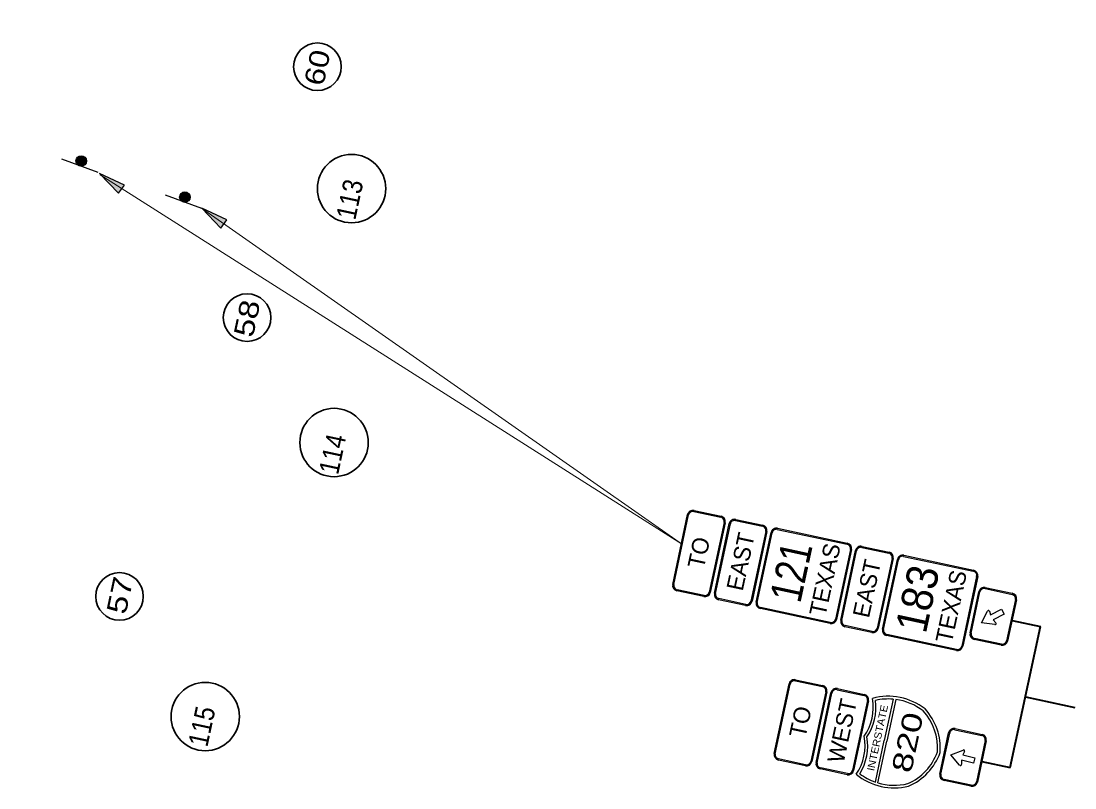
# Model space of a CAD drawing. Extents: x 2363411 to 2369702, y 6977197 to 6988655.
# Drawn here: x 2366110 to 2366856, y 6982468 to 6983011 of the extents above; entities that cross this region are included whole.
import ezdxf
from ezdxf.enums import TextEntityAlignment as Align

# ---------------------------------------------------------------- set-up
doc = ezdxf.new("R2010")
doc.units = 0
doc.header["$LTSCALE"] = 5.6
for name, color, linetype, lineweight in [('1', 7, 'Continuous', 25), ('17', 7, 'Continuous', 35), ('48', 7, 'Continuous', 25)]:
    doc.layers.add(name, color=color, linetype=linetype, lineweight=lineweight)

msp = doc.modelspace()

# ---------------------------------------------------------------- hatches: boundary and pattern name
at = {"layer": '1'}
for points in [[(2366155.643, 6982914.236, 1), (2366150.178, 6982909.153, 1)], [(2366165.758, 6982902.907), (2366179.263, 6982888.795), (2366183.462, 6982894.629)], [(2366228.992, 6982888.681, 1), (2366223.527, 6982883.598, 1)], [(2366238.192, 6982878.216), (2366251.697, 6982864.104), (2366255.896, 6982869.938)]]:
    msp.add_hatch(color=256, dxfattribs=at).paths.add_polyline_path(points)

# ---------------------------------------------------------------- linework, layer by layer
for p, q in [((2366138.982, 6982913.263), (2366164.676, 6982903.831)), ((2366212.331, 6982887.708), (2366238.025, 6982878.276)), ((2366727.069, 6982530.784), (2366720.803, 6982501.447)), ((2366728.961, 6982530.574), (2366722.651, 6982501.055)), ((2366714.536, 6982472.111), (2366720.803, 6982501.447)), ((2366716.344, 6982471.51), (2366722.651, 6982501.055))]:
    msp.add_line(p, q, dxfattribs=at)
at = {"layer": '1', "lineweight": 13}
for p in [(2366166.376, 6982901.97), (2366238.025, 6982878.276)]:
    msp.add_line(p, (2366578.036, 6982640.352), dxfattribs=at)
at = {"layer": '1'}
for points in [[(2366165.758, 6982902.907), (2366179.263, 6982888.795), (2366183.462, 6982894.629)], [(2366238.192, 6982878.216), (2366251.697, 6982864.104), (2366255.896, 6982869.938)]]:
    msp.add_lwpolyline(points, close=True, dxfattribs=at)
for centre in [(2366152.91, 6982911.694), (2366226.26, 6982886.139)]:
    msp.add_circle(centre, 3.732, dxfattribs=at)
at = {"layer": '1', "lineweight": 35}
msp.add_arc((2359877.328, 6985028.058), 6500, 337.9611, 358.49155, dxfattribs=at)
at = {"layer": '1'}
for centre, radius, start, end in [((2366677.098, 6982525.046), 35.984, 325.11936, 9.96967), ((2366677.098, 6982525.046), 37.874, 326.31727, 7.31411), ((2366723.753, 6982490.848), 41.954, 51.80216, 105.50453), ((2366723.753, 6982490.848), 40.064, 85.2486, 103.11335), ((2366723.753, 6982490.848), 40.064, 52.01869, 82.53068), ((2366719.762, 6982496.247), 38.808, 355.77701, 42.42339), ((2366719.762, 6982496.247), 40.698, 355.41087, 42.64677), ((2366671.265, 6982497.75), 35.984, 325.90827, 10.75858), ((2366671.265, 6982497.75), 37.874, 328.56383, 9.56067), ((2366721.973, 6982506.598), 38.808, 293.45455, 340.10093), ((2366721.973, 6982506.598), 40.698, 293.23117, 340.46707), ((2366727.823, 6982509.894), 40.064, 232.76459, 250.62934), ((2366727.823, 6982509.894), 41.954, 230.37341, 284.07578), ((2366727.823, 6982509.894), 40.064, 253.34726, 283.85925)]:
    msp.add_arc(centre, radius, start, end, dxfattribs=at)
at = {"layer": '17'}
for centre, radius in [((2366319.982, 6982978.4), 16.828), ((2366344.093, 6982892.118), 24.19), ((2366270.237, 6982800.82), 16.828), ((2366331.728, 6982712.428), 24.19), ((2366180.014, 6982603.484), 16.828), ((2366240.61, 6982518.479), 24.19)]:
    msp.add_circle(centre, radius, dxfattribs=at)
at = {"layer": '48'}
for p, q in [((2366586.297, 6982664.315), (2366605.38, 6982660.237)), ((2366571.199, 6982612.031), (2366581.739, 6982661.362)), ((2366571.95, 6982611.871), (2366582.491, 6982661.201)), ((2366586.137, 6982663.564), (2366605.219, 6982659.486)), ((2366615.664, 6982657.255), (2366634.746, 6982653.177)), ((2366615.824, 6982658.006), (2366634.907, 6982653.928)), ((2366607.582, 6982655.84), (2366597.041, 6982606.509)), ((2366608.333, 6982655.68), (2366597.792, 6982606.349)), ((2366600.726, 6982605.722), (2366611.267, 6982655.053)), ((2366601.477, 6982605.562), (2366612.018, 6982654.892)), ((2366637.109, 6982649.531), (2366626.568, 6982600.2)), ((2366637.86, 6982649.371), (2366627.319, 6982600.04)), ((2366645.191, 6982650.946), (2366694.521, 6982640.405)), ((2366645.351, 6982651.697), (2366694.682, 6982641.156)), ((2366630.253, 6982599.413), (2366640.794, 6982648.744)), ((2366631.004, 6982599.253), (2366641.545, 6982648.583)), ((2366696.884, 6982636.759), (2366686.343, 6982587.428)), ((2366697.635, 6982636.599), (2366687.094, 6982587.268)), ((2366690.028, 6982586.641), (2366700.568, 6982635.972)), ((2366690.779, 6982586.481), (2366701.319, 6982635.811)), ((2366704.966, 6982638.174), (2366724.048, 6982634.096)), ((2366705.126, 6982638.925), (2366724.209, 6982634.847)), ((2366726.411, 6982630.45), (2366715.87, 6982581.119)), ((2366727.162, 6982630.29), (2366716.621, 6982580.959)), ((2366719.555, 6982580.332), (2366730.095, 6982629.663)), ((2366720.306, 6982580.172), (2366730.846, 6982629.502)), ((2366734.493, 6982631.865), (2366783.823, 6982621.324)), ((2366734.653, 6982632.616), (2366783.984, 6982622.075)), ((2366786.186, 6982617.678), (2366775.645, 6982568.347)), ((2366786.937, 6982617.518), (2366776.396, 6982568.187)), ((2366593.235, 6982603.396), (2366574.152, 6982607.474)), ((2366593.395, 6982604.147), (2366574.312, 6982608.225)), ((2366781.478, 6982577.613), (2366787.722, 6982606.838)), ((2366782.229, 6982577.452), (2366788.474, 6982606.678)), ((2366792.12, 6982609.04), (2366811.202, 6982604.963)), ((2366792.28, 6982609.791), (2366811.363, 6982605.714)), ((2366622.762, 6982597.087), (2366603.679, 6982601.165)), ((2366622.922, 6982597.838), (2366603.839, 6982601.916)), ((2366813.565, 6982601.317), (2366807.32, 6982572.091)), ((2366814.316, 6982601.156), (2366808.071, 6982571.93)), ((2366682.537, 6982584.315), (2366633.206, 6982594.856)), ((2366682.697, 6982585.066), (2366633.366, 6982595.607)), ((2366712.064, 6982578.006), (2366692.981, 6982582.084)), ((2366712.224, 6982578.757), (2366693.141, 6982582.835)), ((2366771.839, 6982565.234), (2366722.508, 6982575.775)), ((2366771.999, 6982565.985), (2366722.668, 6982576.526)), ((2366803.513, 6982568.978), (2366784.431, 6982573.055)), ((2366803.674, 6982569.729), (2366784.591, 6982573.806)), ((2366643.037, 6982492.261), (2366653.577, 6982541.592)), ((2366643.788, 6982492.101), (2366654.328, 6982541.431)), ((2366657.974, 6982543.794), (2366677.057, 6982539.716)), ((2366658.135, 6982544.545), (2366677.217, 6982540.467)), ((2366687.501, 6982537.485), (2366706.584, 6982533.407)), ((2366687.662, 6982538.236), (2366706.744, 6982534.158)), ((2366679.419, 6982536.07), (2366668.879, 6982486.739)), ((2366680.17, 6982535.91), (2366669.63, 6982486.579)), ((2366672.564, 6982485.952), (2366683.104, 6982535.283)), ((2366673.315, 6982485.792), (2366683.855, 6982535.122)), ((2366708.946, 6982529.761), (2366698.406, 6982480.43)), ((2366709.697, 6982529.601), (2366699.157, 6982480.27)), ((2366770.782, 6982509.179), (2366789.865, 6982505.101)), ((2366770.943, 6982509.93), (2366790.026, 6982505.852)), ((2366760.141, 6982477.751), (2366766.385, 6982506.977)), ((2366760.892, 6982477.591), (2366767.136, 6982506.816)), ((2366792.227, 6982501.455), (2366785.983, 6982472.229)), ((2366792.978, 6982501.295), (2366786.734, 6982472.069)), ((2366665.072, 6982483.626), (2366645.989, 6982487.704)), ((2366665.233, 6982484.377), (2366646.15, 6982488.455)), ((2366694.599, 6982477.317), (2366675.516, 6982481.395)), ((2366694.76, 6982478.068), (2366675.677, 6982482.146)), ((2366782.176, 6982469.116), (2366763.093, 6982473.193)), ((2366782.337, 6982469.867), (2366763.254, 6982473.944))]:
    msp.add_line(p, q, dxfattribs=at)
at = {"layer": '48', "lineweight": 40}
for p, q in [((2366809.964, 6982482.385), (2366831.302, 6982582.247)), ((2366811.193, 6982586.543), (2366831.302, 6982582.247)), ((2366820.633, 6982532.316), (2366855.676, 6982524.829)), ((2366789.856, 6982486.682), (2366809.964, 6982482.385))]:
    msp.add_line(p, q, dxfattribs=at)
at = {"layer": '48'}
for points in [[(2366799.108, 6982583.503), (2366789.654, 6982584.683), (2366793.934, 6982593.105)], [(2366795.365, 6982592.942), (2366795.973, 6982590.438), (2366803.792, 6982594.585), (2366805.688, 6982591.012), (2366797.868, 6982586.866), (2366799.786, 6982584.787)], [(2366774.14, 6982484.15), (2366767.859, 6982491.315), (2366776.656, 6982494.764)], [(2366777.616, 6982493.69), (2366776.407, 6982491.414), (2366785.005, 6982489.317), (2366784.048, 6982485.388), (2366775.448, 6982487.485), (2366775.499, 6982484.659)]]:
    msp.add_lwpolyline(points, dxfattribs=at)
for centre, radius, start, end in [((2366585.495, 6982660.559), 3.84, 77.93906, 167.93906), ((2366585.495, 6982660.559), 3.072, 77.93906, 167.93906), ((2366604.577, 6982656.482), 3.072, 347.93906, 77.93906), ((2366604.577, 6982656.482), 3.84, 347.93906, 77.93906), ((2366615.022, 6982654.25), 3.84, 77.93906, 167.93906), ((2366615.022, 6982654.25), 3.072, 77.93906, 167.93906), ((2366634.104, 6982650.173), 3.072, 347.93906, 77.93906), ((2366634.104, 6982650.173), 3.84, 347.93906, 77.93906), ((2366644.549, 6982647.941), 3.84, 77.93906, 167.93906), ((2366644.549, 6982647.941), 3.072, 77.93906, 167.93906), ((2366693.879, 6982637.401), 3.072, 347.93906, 77.93906), ((2366693.879, 6982637.401), 3.84, 347.93906, 77.93906), ((2366704.324, 6982635.169), 3.84, 77.93906, 167.93906), ((2366704.324, 6982635.169), 3.072, 77.93906, 167.93906), ((2366723.406, 6982631.092), 3.84, 347.93906, 77.93906), ((2366723.406, 6982631.092), 3.072, 347.93906, 77.93906), ((2366733.851, 6982628.86), 3.84, 77.93906, 167.93906), ((2366733.851, 6982628.86), 3.072, 77.93906, 167.93906), ((2366783.181, 6982618.32), 3.072, 347.93906, 77.93906), ((2366783.181, 6982618.32), 3.84, 347.93906, 77.93906), ((2366574.954, 6982611.229), 3.84, 167.93906, 257.93906), ((2366574.954, 6982611.229), 3.072, 167.93906, 257.93906), ((2366594.037, 6982607.151), 3.84, 257.93906, 347.93906), ((2366594.037, 6982607.151), 3.072, 257.93906, 347.93906), ((2366604.481, 6982604.92), 3.84, 167.93906, 257.93906), ((2366604.481, 6982604.92), 3.072, 167.93906, 257.93906), ((2366791.478, 6982606.036), 3.84, 77.93906, 167.93906), ((2366791.478, 6982606.036), 3.072, 77.93906, 167.93906), ((2366810.56, 6982601.959), 3.072, 347.93906, 77.93906), ((2366810.56, 6982601.959), 3.84, 347.93906, 77.93906), ((2366623.564, 6982600.842), 3.84, 257.93906, 347.93906), ((2366623.564, 6982600.842), 3.072, 257.93906, 347.93906), ((2366634.008, 6982598.611), 3.84, 167.93906, 257.93906), ((2366634.008, 6982598.611), 3.072, 167.93906, 257.93906), ((2366794.62, 6982592.759), 0.767, 13.43756, 153.07618), ((2366683.339, 6982588.07), 3.84, 257.93906, 347.93906), ((2366683.339, 6982588.07), 3.072, 257.93906, 347.93906), ((2366693.783, 6982585.839), 3.84, 167.93906, 257.93906), ((2366693.783, 6982585.839), 3.072, 167.93906, 257.93906), ((2366799.212, 6982584.263), 0.767, 262.92454, 42.65311), ((2366712.866, 6982581.761), 3.84, 257.93906, 347.93906), ((2366712.866, 6982581.761), 3.072, 257.93906, 347.93906), ((2366723.31, 6982579.53), 3.84, 167.93906, 257.93906), ((2366723.31, 6982579.53), 3.072, 167.93906, 257.93906), ((2366785.233, 6982576.81), 3.84, 167.93906, 257.93906), ((2366785.233, 6982576.81), 3.072, 167.93906, 257.93906), ((2366772.641, 6982568.989), 3.84, 257.93906, 347.93906), ((2366772.641, 6982568.989), 3.072, 257.93906, 347.93906), ((2366804.316, 6982572.733), 3.84, 257.93906, 347.93906), ((2366804.316, 6982572.733), 3.072, 257.93906, 347.93906), ((2366657.332, 6982540.789), 3.84, 77.93906, 167.93906), ((2366657.332, 6982540.789), 3.072, 77.93906, 167.93906), ((2366676.415, 6982536.712), 3.072, 347.93906, 77.93906), ((2366676.415, 6982536.712), 3.84, 347.93906, 77.93906), ((2366686.859, 6982534.48), 3.84, 77.93906, 167.93906), ((2366686.859, 6982534.48), 3.072, 77.93906, 167.93906), ((2366705.942, 6982530.403), 3.072, 347.93906, 77.93906), ((2366705.942, 6982530.403), 3.84, 347.93906, 77.93906), ((2366770.14, 6982506.175), 3.84, 77.93906, 167.93906), ((2366770.14, 6982506.175), 3.072, 77.93906, 167.93906), ((2366789.223, 6982502.097), 3.072, 347.93906, 77.93906), ((2366789.223, 6982502.097), 3.84, 347.93906, 77.93906), ((2366776.937, 6982494.048), 0.767, 331.78631, 111.42492), ((2366646.792, 6982491.459), 3.84, 167.93906, 257.93906), ((2366646.792, 6982491.459), 3.072, 167.93906, 257.93906), ((2366665.875, 6982487.381), 3.84, 257.93906, 347.93906), ((2366665.875, 6982487.381), 3.072, 257.93906, 347.93906), ((2366676.319, 6982485.15), 3.84, 167.93906, 257.93906), ((2366676.319, 6982485.15), 3.072, 167.93906, 257.93906), ((2366695.402, 6982481.072), 3.84, 257.93906, 347.93906), ((2366695.402, 6982481.072), 3.072, 257.93906, 347.93906), ((2366763.896, 6982476.949), 3.84, 167.93906, 257.93906), ((2366774.723, 6982484.647), 0.767, 221.27328, 1.00186), ((2366763.896, 6982476.949), 3.072, 167.93906, 257.93906), ((2366782.979, 6982472.871), 3.84, 257.93906, 347.93906), ((2366782.979, 6982472.871), 3.072, 257.93906, 347.93906)]:
    msp.add_arc(centre, radius, start, end, dxfattribs=at)

# ---------------------------------------------------------------- texts
at = {"layer": '1'}
for s, height, width, p in [('INTERSTATE', 5.198, 1.1, (2366713.655, 6982479.581)), ('820', 14.18, 1.35, (2366739.724, 6982477.831))]:
    msp.add_text(s, height=height, rotation=77.939, dxfattribs=dict(at, width=width)).set_placement(p)
at = {"layer": '17'}
for s, width, p in [('60', 1.2, (2366326.702, 6982976.359)), ('113', 0.9, (2366349.628, 6982883.064)), ('58', 1.25, (2366276.97, 6982798.832)), ('114', 0.9, (2366337.494, 6982702.833)), ('57', 1.25, (2366187.034, 6982602.841)), ('115', 0.9, (2366245.023, 6982510.081))]:
    msp.add_text(s, height=14, rotation=77.939, dxfattribs=dict(at, width=width)).set_placement(p, align=Align.CENTER)
at = {"layer": '48'}
for s, p in [('EAST', (2366625.007, 6982626.951)), ('TO', (2366595.481, 6982633.26)), ('TEXAS', (2366684.671, 6982614.202)), ('EAST', (2366714.309, 6982607.869)), ('TEXAS', (2366773.972, 6982595.121)), ('WEST', (2366696.845, 6982507.181)), ('TO', (2366667.317, 6982513.491))]:
    msp.add_text(s, height=11.82, rotation=77.859, dxfattribs=at).set_placement(p, align=Align.CENTER)
for s, width, p in [('121', 0.85, (2366665.83, 6982618.556)), ('183', 0.95, (2366755.131, 6982599.476))]:
    msp.add_text(s, height=22.16, rotation=77.859, dxfattribs=dict(at, width=width)).set_placement(p, align=Align.CENTER)

doc.saveas('drawing.dxf')
